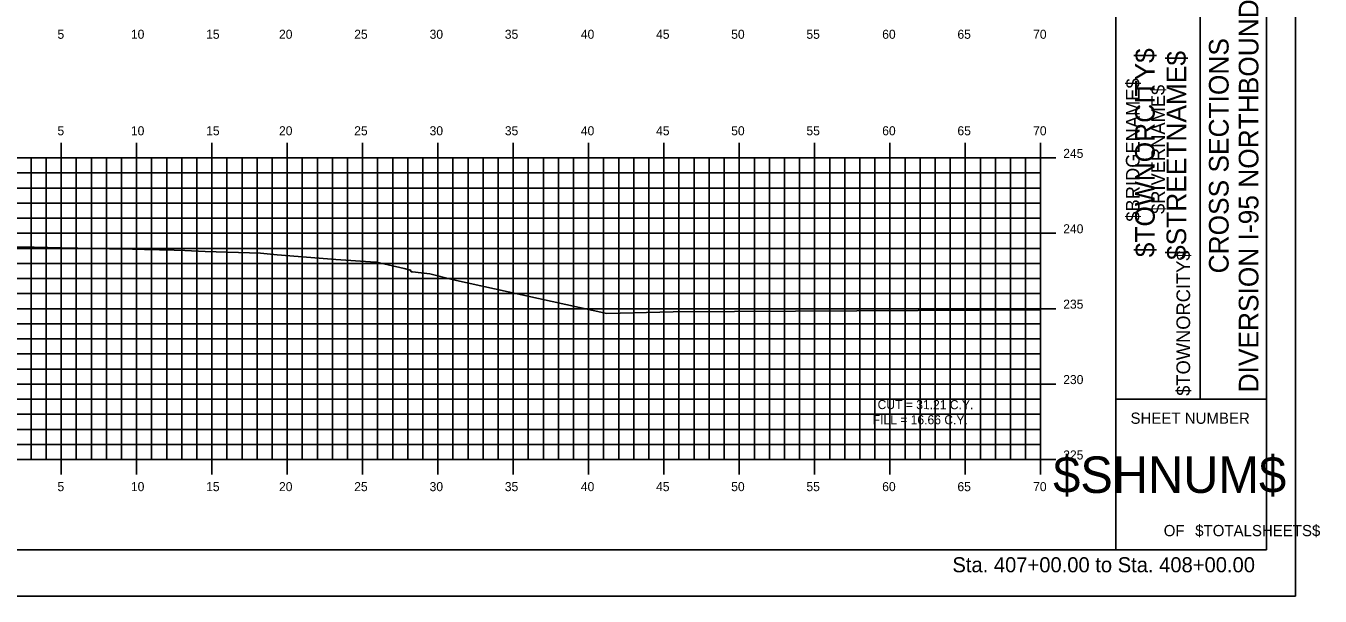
# Model space of a CAD drawing. Extents: x 1160718 to 1173142, y 616002 to 617630.
# Drawn here: x 1167304 to 1167389.9, y 616613.9 to 616651.7 of the extents above; entities that cross this region are included whole.
import ezdxf

# ---------------------------------------------------------------- set-up
doc = ezdxf.new("R2010")
doc.units = 0
for name, color, linetype in [('ANNOTATION', 7, 'Continuous'), ('BORDER', 7, 'Continuous'), ('BRIDGE_TITLE', 7, 'Continuous'), ('H_V ANNOTATION', 7, 'Continuous'), ('HIGHWAY_TITLE', 7, 'Continuous'), ('MAJOR', 7, 'Continuous'), ('MINOR', 7, 'Continuous'), ('PLOT BOUNDARY', 7, 'Continuous'), ('S_Roadway_Centerline', 7, 'Continuous')]:
    doc.layers.add(name, color=color, linetype=linetype)

msp = doc.modelspace()

# ---------------------------------------------------------------- linework, layer by layer
at = {"layer": 'BORDER'}
for p, q in [((1167376.316, 616616.931), (1167376.316, 616721.931)), ((1167386.316, 616616.931), (1167386.316, 616721.931)), ((1167381.907, 616626.931), (1167381.907, 616661.931)), ((1167376.316, 616626.931), (1167386.316, 616626.931)), ((1167226.316, 616616.928), (1167386.316, 616616.928))]:
    msp.add_line(p, q, dxfattribs=at)
at = {"layer": 'MAJOR'}
for p, q in [((1167306.315, 616643.93), (1167306.315, 616642.928)), ((1167311.315, 616643.93), (1167311.315, 616642.928)), ((1167316.315, 616643.93), (1167316.315, 616642.928)), ((1167321.315, 616643.93), (1167321.315, 616642.928)), ((1167326.315, 616643.93), (1167326.315, 616642.928)), ((1167331.315, 616643.93), (1167331.315, 616642.928)), ((1167336.315, 616643.93), (1167336.315, 616642.928)), ((1167341.315, 616643.93), (1167341.315, 616642.928)), ((1167346.315, 616643.93), (1167346.315, 616642.928)), ((1167351.315, 616643.93), (1167351.315, 616642.928)), ((1167356.315, 616643.93), (1167356.315, 616642.928)), ((1167361.315, 616643.93), (1167361.315, 616642.928)), ((1167366.315, 616643.93), (1167366.315, 616642.928)), ((1167371.315, 616643.93), (1167371.315, 616642.928)), ((1167231.315, 616642.928), (1167371.315, 616642.928)), ((1167231.315, 616642.928), (1167371.315, 616642.928)), ((1167306.315, 616622.928), (1167306.315, 616642.928)), ((1167311.315, 616622.928), (1167311.315, 616642.928)), ((1167316.315, 616622.928), (1167316.315, 616642.928)), ((1167321.315, 616622.928), (1167321.315, 616642.928)), ((1167326.315, 616622.928), (1167326.315, 616642.928)), ((1167331.315, 616622.928), (1167331.315, 616642.928)), ((1167336.315, 616622.928), (1167336.315, 616642.928)), ((1167341.315, 616622.928), (1167341.315, 616642.928)), ((1167346.315, 616622.928), (1167346.315, 616642.928)), ((1167351.315, 616622.928), (1167351.315, 616642.928)), ((1167356.315, 616622.928), (1167356.315, 616642.928)), ((1167361.315, 616622.928), (1167361.315, 616642.928)), ((1167366.315, 616622.928), (1167366.315, 616642.928)), ((1167372.317, 616642.928), (1167370.313, 616642.928)), ((1167371.315, 616622.928), (1167371.315, 616642.928)), ((1167371.315, 616622.928), (1167371.315, 616642.928)), ((1167231.315, 616637.928), (1167371.315, 616637.928)), ((1167372.317, 616637.928), (1167370.313, 616637.928)), ((1167231.315, 616632.928), (1167371.315, 616632.928)), ((1167372.317, 616632.928), (1167370.313, 616632.928)), ((1167231.315, 616627.928), (1167371.315, 616627.928)), ((1167372.317, 616627.928), (1167370.313, 616627.928)), ((1167231.315, 616622.928), (1167371.315, 616622.928)), ((1167231.315, 616622.928), (1167371.315, 616622.928)), ((1167306.315, 616621.926), (1167306.315, 616622.928)), ((1167311.315, 616621.926), (1167311.315, 616622.928)), ((1167316.315, 616621.926), (1167316.315, 616622.928)), ((1167321.315, 616621.926), (1167321.315, 616622.928)), ((1167326.315, 616621.926), (1167326.315, 616622.928)), ((1167331.315, 616621.926), (1167331.315, 616622.928)), ((1167336.315, 616621.926), (1167336.315, 616622.928)), ((1167341.315, 616621.926), (1167341.315, 616622.928)), ((1167346.315, 616621.926), (1167346.315, 616622.928)), ((1167351.315, 616621.926), (1167351.315, 616622.928)), ((1167356.315, 616621.926), (1167356.315, 616622.928)), ((1167361.315, 616621.926), (1167361.315, 616622.928)), ((1167366.315, 616621.926), (1167366.315, 616622.928)), ((1167372.317, 616622.928), (1167370.313, 616622.928)), ((1167371.315, 616621.926), (1167371.315, 616622.928))]:
    msp.add_line(p, q, dxfattribs=at)
at = {"layer": 'MINOR'}
for p, q in [((1167304.315, 616622.928), (1167304.315, 616642.928)), ((1167305.315, 616622.928), (1167305.315, 616642.928)), ((1167307.315, 616622.928), (1167307.315, 616642.928)), ((1167308.315, 616622.928), (1167308.315, 616642.928)), ((1167309.315, 616622.928), (1167309.315, 616642.928)), ((1167310.315, 616622.928), (1167310.315, 616642.928)), ((1167312.315, 616622.928), (1167312.315, 616642.928)), ((1167313.315, 616622.928), (1167313.315, 616642.928)), ((1167314.315, 616622.928), (1167314.315, 616642.928)), ((1167315.315, 616622.928), (1167315.315, 616642.928)), ((1167317.315, 616622.928), (1167317.315, 616642.928)), ((1167318.315, 616622.928), (1167318.315, 616642.928)), ((1167319.315, 616622.928), (1167319.315, 616642.928)), ((1167320.315, 616622.928), (1167320.315, 616642.928)), ((1167322.315, 616622.928), (1167322.315, 616642.928)), ((1167323.315, 616622.928), (1167323.315, 616642.928)), ((1167324.315, 616622.928), (1167324.315, 616642.928)), ((1167325.315, 616622.928), (1167325.315, 616642.928)), ((1167327.315, 616622.928), (1167327.315, 616642.928)), ((1167328.315, 616622.928), (1167328.315, 616642.928)), ((1167329.315, 616622.928), (1167329.315, 616642.928)), ((1167330.315, 616622.928), (1167330.315, 616642.928)), ((1167332.315, 616622.928), (1167332.315, 616642.928)), ((1167333.315, 616622.928), (1167333.315, 616642.928)), ((1167334.315, 616622.928), (1167334.315, 616642.928)), ((1167335.315, 616622.928), (1167335.315, 616642.928)), ((1167337.315, 616622.928), (1167337.315, 616642.928)), ((1167338.315, 616622.928), (1167338.315, 616642.928)), ((1167339.315, 616622.928), (1167339.315, 616642.928)), ((1167340.315, 616622.928), (1167340.315, 616642.928)), ((1167342.315, 616622.928), (1167342.315, 616642.928)), ((1167343.315, 616622.928), (1167343.315, 616642.928)), ((1167344.315, 616622.928), (1167344.315, 616642.928)), ((1167345.315, 616622.928), (1167345.315, 616642.928)), ((1167347.315, 616622.928), (1167347.315, 616642.928)), ((1167348.315, 616622.928), (1167348.315, 616642.928)), ((1167349.315, 616622.928), (1167349.315, 616642.928)), ((1167350.315, 616622.928), (1167350.315, 616642.928)), ((1167352.315, 616622.928), (1167352.315, 616642.928)), ((1167353.315, 616622.928), (1167353.315, 616642.928)), ((1167354.315, 616622.928), (1167354.315, 616642.928)), ((1167355.315, 616622.928), (1167355.315, 616642.928)), ((1167357.315, 616622.928), (1167357.315, 616642.928)), ((1167358.315, 616622.928), (1167358.315, 616642.928)), ((1167359.315, 616622.928), (1167359.315, 616642.928)), ((1167360.315, 616622.928), (1167360.315, 616642.928)), ((1167362.315, 616622.928), (1167362.315, 616642.928)), ((1167363.315, 616622.928), (1167363.315, 616642.928)), ((1167364.315, 616622.928), (1167364.315, 616642.928)), ((1167365.315, 616622.928), (1167365.315, 616642.928)), ((1167367.315, 616622.928), (1167367.315, 616642.928)), ((1167368.315, 616622.928), (1167368.315, 616642.928)), ((1167369.315, 616622.928), (1167369.315, 616642.928)), ((1167370.315, 616622.928), (1167370.315, 616642.928)), ((1167231.315, 616641.928), (1167371.315, 616641.928)), ((1167371.315, 616641.928), (1167370.313, 616641.928)), ((1167231.315, 616640.928), (1167371.315, 616640.928)), ((1167371.315, 616640.928), (1167370.313, 616640.928)), ((1167231.315, 616639.928), (1167371.315, 616639.928)), ((1167371.315, 616639.928), (1167370.313, 616639.928)), ((1167231.315, 616638.928), (1167371.315, 616638.928)), ((1167371.315, 616638.928), (1167370.313, 616638.928)), ((1167231.315, 616636.928), (1167371.315, 616636.928)), ((1167371.315, 616636.928), (1167370.313, 616636.928)), ((1167231.315, 616635.928), (1167371.315, 616635.928)), ((1167371.315, 616635.928), (1167370.313, 616635.928)), ((1167231.315, 616634.928), (1167371.315, 616634.928)), ((1167371.315, 616634.928), (1167370.313, 616634.928)), ((1167231.315, 616633.928), (1167371.315, 616633.928)), ((1167371.315, 616633.928), (1167370.313, 616633.928)), ((1167231.315, 616631.928), (1167371.315, 616631.928)), ((1167371.315, 616631.928), (1167370.313, 616631.928)), ((1167231.315, 616630.928), (1167371.315, 616630.928)), ((1167371.315, 616630.928), (1167370.313, 616630.928)), ((1167231.315, 616629.928), (1167371.315, 616629.928)), ((1167371.315, 616629.928), (1167370.313, 616629.928)), ((1167231.315, 616628.928), (1167371.315, 616628.928)), ((1167371.315, 616628.928), (1167370.313, 616628.928)), ((1167231.315, 616626.928), (1167371.315, 616626.928)), ((1167371.315, 616626.928), (1167370.313, 616626.928)), ((1167231.315, 616625.928), (1167371.315, 616625.928)), ((1167371.315, 616625.928), (1167370.313, 616625.928)), ((1167231.315, 616624.928), (1167371.315, 616624.928)), ((1167371.315, 616624.928), (1167370.313, 616624.928)), ((1167231.315, 616623.928), (1167371.315, 616623.928)), ((1167371.315, 616623.928), (1167370.313, 616623.928))]:
    msp.add_line(p, q, dxfattribs=at)
at = {"layer": 'PLOT BOUNDARY'}
msp.add_lwpolyline([(1167218.222, 616613.869), (1167388.222, 616613.869), (1167388.222, 616723.869), (1167218.222, 616723.869)], close=True, dxfattribs=at)
at = {"layer": 'S_Roadway_Centerline'}
msp.add_lwpolyline([(1167301.607, 616637.05), (1167304.516, 616636.999), (1167306.364, 616636.964), (1167309.522, 616636.905), (1167311.04, 616636.872), (1167311.841, 616636.855), (1167313.802, 616636.799), (1167314.529, 616636.778), (1167315.88, 616636.729), (1167319.536, 616636.6), (1167320.637, 616636.51), (1167324.543, 616636.186), (1167326.85, 616636.047), (1167327.235, 616636.023), (1167329.078, 616635.595), (1167329.505, 616635.494), (1167329.546, 616635.377), (1167329.621, 616635.378), (1167330.772, 616635.236), (1167332.343, 616634.85), (1167342.531, 616632.608), (1167346.936, 616632.719), (1167371.315, 616632.857)], dxfattribs=at)

# ---------------------------------------------------------------- texts
at = {"layer": 'ANNOTATION'}
for s, p in [('CUT = 31.21 C.Y.', (1167360.495, 616626.27)), ('FILL = 16.66 C.Y.', (1167360.172, 616625.269))]:
    msp.add_text(s, height=0.6, rotation=359.92408, dxfattribs=at).set_placement(p)
at = {"layer": 'BORDER'}
for s, height, rotation, p in [('DIVERSION I-95 NORTHBOUND  ', 1.30428, 90, (1167385.77, 616627.379)), ('CROSS SECTIONS', 1.30428, 90, (1167383.791, 616635.27)), ('SHEET NUMBER', 0.74527, 360, (1167377.281, 616625.295)), ('$SHNUM$', 2.4194, 360, (1167372.149, 616620.711)), ('OF', 0.7453, 360, (1167379.483, 616617.841)), ('$TOTALSHEETS$', 0.74527, 360, (1167381.572, 616617.841))]:
    msp.add_text(s, height=height, rotation=rotation, dxfattribs=at).set_placement(p)
at = {"layer": 'BRIDGE_TITLE'}
for s, p in [('$BRIDGENAME$', (1167377.882, 616638.7)), ('$RIVERNAME$', (1167379.559, 616639.214)), ('$TOWNORCITY$', (1167381.236, 616627.152))]:
    msp.add_text(s, height=0.90716, rotation=90, dxfattribs=at).set_placement(p)
at = {"layer": 'H_V ANNOTATION'}
for s, height, p in [('5', 0.6, (1167306.066, 616650.828)), ('10', 0.6, (1167310.941, 616650.828)), ('15', 0.6, (1167315.933, 616650.828)), ('20', 0.6, (1167320.769, 616650.828)), ('25', 0.6, (1167325.761, 616650.828)), ('30', 0.6, (1167330.764, 616650.828)), ('35', 0.6, (1167335.756, 616650.828)), ('40', 0.6, (1167340.802, 616650.828)), ('45', 0.6, (1167345.794, 616650.828)), ('50', 0.6, (1167350.78, 616650.828)), ('55', 0.6, (1167355.772, 616650.828)), ('60', 0.6, (1167360.802, 616650.828)), ('65', 0.6, (1167365.794, 616650.828)), ('70', 0.6, (1167370.818, 616650.828)), ('5', 0.6, (1167306.066, 616644.428)), ('10', 0.6, (1167310.941, 616644.428)), ('15', 0.6, (1167315.933, 616644.428)), ('20', 0.6, (1167320.769, 616644.428)), ('25', 0.6, (1167325.761, 616644.428)), ('30', 0.6, (1167330.764, 616644.428)), ('35', 0.6, (1167335.756, 616644.428)), ('40', 0.6, (1167340.802, 616644.428)), ('45', 0.6, (1167345.794, 616644.428)), ('50', 0.6, (1167350.78, 616644.428)), ('55', 0.6, (1167355.772, 616644.428)), ('60', 0.6, (1167360.802, 616644.428)), ('65', 0.6, (1167365.794, 616644.428)), ('70', 0.6, (1167370.818, 616644.428)), ('245', 0.6, (1167372.815, 616642.928)), ('240', 0.6, (1167372.815, 616637.928)), ('235', 0.6, (1167372.815, 616632.928)), ('230', 0.6, (1167372.815, 616627.928)), ('225', 0.6, (1167372.815, 616622.928)), ('5', 0.6, (1167306.066, 616620.828)), ('10', 0.6, (1167310.941, 616620.828)), ('15', 0.6, (1167315.933, 616620.828)), ('20', 0.6, (1167320.769, 616620.828)), ('25', 0.6, (1167325.761, 616620.828)), ('30', 0.6, (1167330.764, 616620.828)), ('35', 0.6, (1167335.756, 616620.828)), ('40', 0.6, (1167340.802, 616620.828)), ('45', 0.6, (1167345.794, 616620.828)), ('50', 0.6, (1167350.78, 616620.828)), ('55', 0.6, (1167355.772, 616620.828)), ('60', 0.6, (1167360.802, 616620.828)), ('65', 0.6, (1167365.794, 616620.828)), ('70', 0.6, (1167370.818, 616620.828)), ('Sta. 407+00.00 to Sta. 408+00.00', 1.0002, (1167365.461, 616615.448))]:
    msp.add_text(s, height=height, dxfattribs=at).set_placement(p)
at = {"layer": 'HIGHWAY_TITLE'}
for s, p in [('$TOWNORCITY$', (1167378.888, 616636.34)), ('$STREETNAME$', (1167380.975, 616636.16))]:
    msp.add_text(s, height=1.30428, rotation=90, dxfattribs=at).set_placement(p)

doc.saveas('drawing.dxf')
